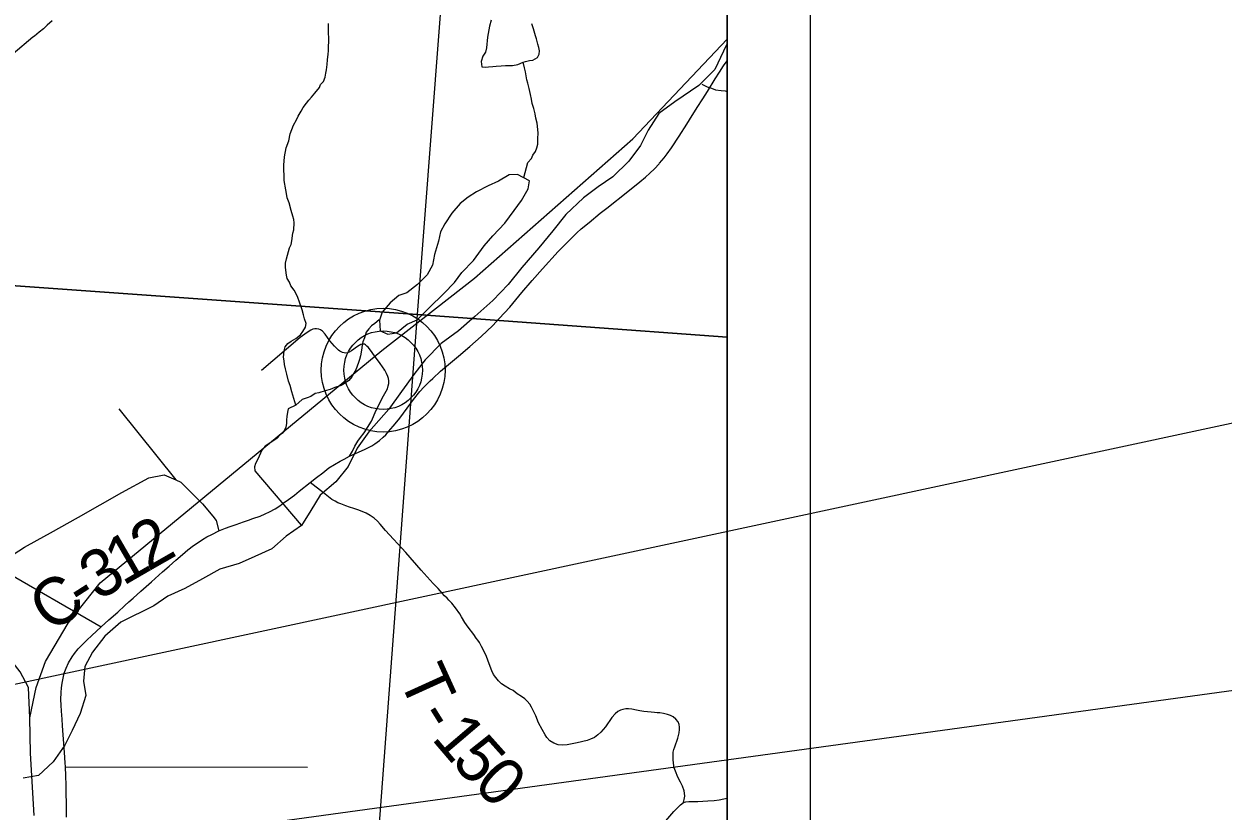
# Model space of a CAD drawing. Extents: x 0 to 44, y -23.8 to 22.
# Drawn here: x 8.055 to 9.496, y 17.755 to 18.701 of the extents above; entities that cross this region are included whole.
import ezdxf

# ---------------------------------------------------------------- set-up
doc = ezdxf.new("R2010")
doc.units = 0
for name, color, linetype in [('Default', 7, 'Continuous'), ('GM_X_County_Road', 7, 'Continuous'), ('GM_X_County_Road_Text', 7, 'Continuous'), ('GM_X_Minor_Lake', 7, 'Continuous'), ('GM_X_Minor_River', 7, 'Continuous'), ('GM_X_Rail_Line', 7, 'Continuous'), ('GM_X_Section', 7, 'Continuous'), ('GM_X_State_Route', 7, 'Continuous'), ('GM_X_Township_Road', 7, 'Continuous'), ('GM_X_Township_Road_Text', 7, 'Continuous'), ('GM_X_Unincorporated', 7, 'Continuous'), ('GM_X_Unincorporated_Location', 7, 'Continuous'), ('SH_Cut_Line', 7, 'Continuous'), ('SH_Data', 7, 'Continuous')]:
    doc.layers.add(name, color=color, linetype=linetype)

msp = doc.modelspace()

# ---------------------------------------------------------------- linework, layer by layer
at = {"layer": 'Default'}
msp.add_lwpolyline([(7.2787, 14.3616), (7.5613, 14.343), (8.045, 14.3111), (8.4778, 14.2825), (8.9, 14.2547), (8.9, 20.3521), (8.6785, 20.3684), (7.6577, 20.4476), (7.4495, 20.4611), (7.016, 20.4891)], dxfattribs=at)
for points in [[(8.9, 18.3242), (8.9, 19.3386), (8.6049, 19.3603), (8.5278, 18.3516)], [(8.9, 17.3085), (8.9, 18.3242), (8.5278, 18.3516), (8.4522, 17.3376)]]:
    msp.add_lwpolyline(points, close=True, dxfattribs=at)
at = {"layer": 'GM_X_County_Road'}
for points in [[(8.0828, 18.0867), (8.0837, 18.0872), (8.0873, 18.0892), (8.1208, 18.1078), (8.173, 18.1377), (8.2054, 18.1551), (8.224, 18.1588), (8.238, 18.1527), (8.2439, 18.1501), (8.27, 18.124), (8.2824, 18.1091), (8.2862, 18.1041), (8.2893, 18.0915)], [(8.0274, 18.0459), (8.0425, 18.0631), (8.0562, 18.0718), (8.0828, 18.0867)]]:
    msp.add_lwpolyline(points, dxfattribs=at)
at = {"layer": 'GM_X_Minor_Lake'}
for points in [[(8.6627, 18.512), (8.6483, 18.5196), (8.6384, 18.5192), (8.6255, 18.5116), (8.6129, 18.5059), (8.5989, 18.4987), (8.589, 18.4926), (8.5795, 18.485), (8.5696, 18.4733), (8.5608, 18.4603), (8.5559, 18.4508), (8.5532, 18.4394), (8.5486, 18.4235), (8.546, 18.4109), (8.5399, 18.3992), (8.5281, 18.3874), (8.5155, 18.3775), (8.5056, 18.3745), (8.4954, 18.3657), (8.4859, 18.3544), (8.4824, 18.3448), (8.4832, 18.3319), (8.4927, 18.3277), (8.503, 18.3296), (8.5159, 18.3399), (8.5277, 18.3452), (8.5421, 18.3596), (8.5596, 18.3767), (8.5725, 18.39), (8.5813, 18.4018), (8.5954, 18.4162), (8.6083, 18.4341), (8.6186, 18.4459), (8.633, 18.4614), (8.6444, 18.4766), (8.6532, 18.4884), (8.6612, 18.5025), (8.6627, 18.512)], [(8.4954, 18.3657), (8.4859, 18.3544), (8.4824, 18.3448), (8.4832, 18.3319), (8.4927, 18.3277), (8.503, 18.3296), (8.5159, 18.3399), (8.5277, 18.3452), (8.5421, 18.3596), (8.5596, 18.3767), (8.5725, 18.39), (8.5813, 18.4018), (8.5954, 18.4162), (8.6083, 18.4341), (8.6186, 18.4459), (8.633, 18.4614), (8.6444, 18.4766), (8.6532, 18.4884), (8.6612, 18.5025), (8.6627, 18.512)], [(8.6627, 18.512), (8.6483, 18.5196), (8.6384, 18.5192), (8.6255, 18.5116), (8.6129, 18.5059), (8.5989, 18.4987), (8.589, 18.4926), (8.5795, 18.485), (8.5696, 18.4733), (8.5608, 18.4603), (8.5559, 18.4508), (8.5532, 18.4394), (8.5486, 18.4235), (8.546, 18.4109), (8.5399, 18.3992), (8.5281, 18.3874), (8.5155, 18.3775), (8.5056, 18.3745), (8.4954, 18.3657)]]:
    msp.add_lwpolyline(points, dxfattribs=at)
at = {"layer": 'GM_X_Minor_River'}
for points in [[(8.382, 18.2426), (8.3772, 18.2586), (8.375, 18.2662), (8.3732, 18.2712), (8.371, 18.2796), (8.3696, 18.2861), (8.3685, 18.2914), (8.3678, 18.296), (8.3671, 18.3002), (8.3679, 18.3077), (8.3691, 18.3127), (8.3722, 18.3168), (8.3764, 18.3194), (8.3821, 18.3228), (8.3875, 18.3269), (8.3902, 18.331), (8.3937, 18.3363), (8.3945, 18.3405), (8.3926, 18.3462), (8.3912, 18.3511), (8.3894, 18.3569), (8.3883, 18.3607), (8.3868, 18.3653), (8.3839, 18.3733), (8.3798, 18.3809), (8.376, 18.3859), (8.3742, 18.3905), (8.3716, 18.3947), (8.3709, 18.3989), (8.3695, 18.408), (8.3695, 18.4133), (8.3707, 18.4183), (8.3743, 18.4315), (8.3762, 18.4357), (8.377, 18.4398), (8.3783, 18.4493), (8.3795, 18.4531), (8.3799, 18.4615), (8.3796, 18.4657), (8.3785, 18.4695), (8.3763, 18.4763), (8.3741, 18.4855), (8.3716, 18.4916), (8.3709, 18.4969), (8.3698, 18.5011), (8.368, 18.5125), (8.3675, 18.5315), (8.3679, 18.5357), (8.3683, 18.541), (8.3704, 18.5516), (8.3735, 18.5603), (8.3751, 18.5687), (8.379, 18.5789), (8.3829, 18.5853), (8.3848, 18.5898), (8.3883, 18.5959), (8.391, 18.6004), (8.3949, 18.6053), (8.3976, 18.609), (8.401, 18.6128), (8.4049, 18.6173), (8.4103, 18.6241), (8.4118, 18.6279), (8.4153, 18.6316), (8.4172, 18.6365), (8.4181, 18.6415), (8.4189, 18.6456), (8.4197, 18.6517), (8.4201, 18.6574), (8.421, 18.6642), (8.4214, 18.6684), (8.4216, 18.6847), (8.4213, 18.6889), (8.4214, 18.7011)], [(8.6168, 18.7051), (8.6148, 18.6979), (8.6129, 18.6892), (8.6124, 18.6846), (8.6111, 18.6721), (8.6099, 18.6668), (8.6068, 18.6619), (8.6045, 18.6554), (8.6056, 18.649), (8.6093, 18.6485), (8.6135, 18.6489), (8.6188, 18.6496), (8.6226, 18.6499), (8.6287, 18.6502), (8.6337, 18.6505), (8.6382, 18.6505), (8.6424, 18.6508), (8.6488, 18.6518), (8.6552, 18.6546)], [(8.6552, 18.6546), (8.658, 18.6555), (8.6626, 18.6566), (8.6667, 18.6569), (8.6725, 18.6603), (8.6744, 18.6641), (8.6748, 18.6682), (8.6741, 18.6724), (8.6726, 18.6762), (8.6712, 18.6827), (8.6701, 18.6865), (8.6675, 18.6949), (8.6657, 18.7006)], [(8.9, 18.6772), (8.8957, 18.6679), (8.8853, 18.6459), (8.8662, 18.6267), (8.8373, 18.6071), (8.8182, 18.5931), (8.8052, 18.5731), (8.796, 18.5545), (8.7822, 18.5356), (8.7627, 18.5167), (8.7452, 18.505), (8.7277, 18.4915), (8.7063, 18.4715), (8.6906, 18.4522), (8.6738, 18.4314), (8.6535, 18.4079), (8.6371, 18.3875), (8.6188, 18.3682), (8.597, 18.349), (8.5776, 18.332), (8.5566, 18.3166), (8.5375, 18.2969), (8.5237, 18.2795), (8.5088, 18.2591), (8.4939, 18.2379), (8.4698, 18.2103), (8.4556, 18.191), (8.4449, 18.1687), (8.43, 18.1505), (8.4113, 18.1343), (8.4002, 18.1161), (8.3887, 18.098), (8.3704, 18.0851), (8.3532, 18.07), (8.3327, 18.0607), (8.314, 18.0524), (8.2905, 18.0453), (8.2699, 18.034), (8.2486, 18.0224), (8.2284, 18.013), (8.2113, 18.0013), (8.1717, 17.9817), (8.1526, 17.9651), (8.1377, 17.9458), (8.1285, 17.9284), (8.1269, 17.911), (8.1298, 17.8935), (8.1228, 17.8719), (8.1132, 17.8518), (8.1044, 17.834), (8.0906, 17.814), (8.073, 17.7977), (8.0544, 17.7944)], [(8.656, 18.516), (8.6608, 18.5343), (8.665, 18.5388), (8.6666, 18.543), (8.67, 18.5475), (8.6716, 18.5516), (8.6728, 18.5562), (8.6729, 18.5626), (8.6733, 18.5698), (8.6719, 18.5813), (8.6705, 18.5874), (8.6694, 18.5927), (8.668, 18.5992), (8.6661, 18.6049), (8.6651, 18.6102), (8.664, 18.6159), (8.6622, 18.6232), (8.6607, 18.6293), (8.6596, 18.6335), (8.6586, 18.6384), (8.6578, 18.643), (8.6568, 18.6479), (8.6552, 18.6546)], [(8.8697, 18.6281), (8.8762, 18.625), (8.8815, 18.6234), (8.886, 18.6215), (8.8928, 18.6206), (8.8977, 18.6202), (8.9, 18.6196)], [(8.4822, 18.3451), (8.4768, 18.3406), (8.473, 18.338), (8.4695, 18.3342), (8.4664, 18.3304), (8.4645, 18.3236), (8.4625, 18.3187), (8.4617, 18.3145), (8.4609, 18.3088), (8.4597, 18.302), (8.4585, 18.2975), (8.4573, 18.2937), (8.4557, 18.2895), (8.4542, 18.285), (8.4515, 18.2809), (8.4491, 18.2767), (8.4457, 18.2722), (8.4403, 18.2685), (8.4365, 18.2662), (8.4289, 18.2637), (8.4232, 18.2615), (8.4174, 18.2596), (8.4095, 18.2574), (8.4053, 18.2564), (8.3999, 18.253), (8.3957, 18.2515), (8.3896, 18.2493), (8.382, 18.2426), (8.3728, 18.2382), (8.372, 18.234), (8.3712, 18.2291), (8.3708, 18.2249), (8.3707, 18.2207), (8.3699, 18.2162), (8.3668, 18.2094), (8.363, 18.2067), (8.3595, 18.203), (8.3545, 18.1992), (8.3499, 18.1966), (8.345, 18.1933), (8.3411, 18.1884), (8.3364, 18.1778), (8.3334, 18.1725), (8.3322, 18.1684), (8.3329, 18.1638), (8.3882, 18.0985)]]:
    msp.add_lwpolyline(points, dxfattribs=at)
at = {"layer": 'GM_X_Rail_Line'}
for points in [[(8.0624, 17.8667), (8.0701, 17.9031), (8.0811, 17.9347), (8.1085, 17.9806), (8.147, 18.0292), (8.4854, 18.3083), (8.5968, 18.3951), (8.787, 18.5626), (8.9, 18.6825)], [(8.0624, 17.8667), (8.061, 17.9033), (8.051, 17.922), (8.0356, 17.9418), (8.0181, 17.9517), (7.6833, 18.0613), (7.4877, 18.1275), (7.4357, 18.1458), (7.4001, 18.1557), (7.3576, 18.1574), (7.3191, 18.1482)], [(8.0676, 17.7494), (8.0634, 17.8242), (8.0624, 17.8667)]]:
    msp.add_lwpolyline(points, dxfattribs=at)
at = {"layer": 'GM_X_Section'}
for points in [[(7.5875, 19.4351), (8.6049, 19.3603), (8.5278, 18.3516), (7.5123, 18.4238)], [(7.5123, 18.4238), (8.5278, 18.3516), (8.4522, 17.3376), (7.4446, 17.3999)]]:
    msp.add_lwpolyline(points, close=True, dxfattribs=at)
at = {"layer": 'GM_X_State_Route'}
for points in [[(8.0892, 18.7044), (8.0834, 18.6991), (8.0788, 18.6948), (8.0736, 18.6909), (8.0679, 18.686), (8.066, 18.6846), (8.0422, 18.6645)], [(8.1481, 17.9761), (8.1575, 17.9845), (8.1681, 17.994), (8.1766, 18.002), (8.1814, 18.0061), (8.1864, 18.0106), (8.1957, 18.0189), (8.2087, 18.0304), (8.222, 18.0423), (8.2297, 18.049), (8.2379, 18.0564), (8.2457, 18.0631), (8.2524, 18.0688), (8.2591, 18.074), (8.2646, 18.0776), (8.2697, 18.0811), (8.2752, 18.0843), (8.281, 18.0873), (8.2893, 18.0915), (8.2976, 18.0948), (8.3032, 18.0968), (8.3103, 18.0993), (8.319, 18.1022), (8.3252, 18.1045), (8.3304, 18.1062), (8.3393, 18.1093), (8.345, 18.1118), (8.3502, 18.1142), (8.357, 18.118), (8.3628, 18.1214), (8.3667, 18.1246), (8.3732, 18.1292), (8.3803, 18.1343), (8.3859, 18.1392), (8.3992, 18.1496), (8.4068, 18.1555), (8.4143, 18.1614), (8.4218, 18.1674), (8.4285, 18.1713), (8.4352, 18.1753), (8.4399, 18.1778), (8.4464, 18.1811), (8.4653, 18.1898), (8.4685, 18.1913), (8.4732, 18.1936), (8.477, 18.1961), (8.4824, 18.2001), (8.4868, 18.2039), (8.4901, 18.207), (8.4939, 18.2111), (8.5014, 18.22), (8.507, 18.227), (8.5158, 18.2389), (8.5234, 18.2492), (8.5311, 18.259), (8.5358, 18.2642), (8.5434, 18.2718), (8.5464, 18.2747), (8.5559, 18.2833), (8.5679, 18.2934), (8.5775, 18.3016), (8.5912, 18.3129), (8.6047, 18.325), (8.6188, 18.3383), (8.6261, 18.3465), (8.6389, 18.3604), (8.6534, 18.3778), (8.6659, 18.3924), (8.6782, 18.4062), (8.6972, 18.427), (8.709, 18.4393), (8.7151, 18.4453), (8.7196, 18.4496), (8.7248, 18.4544), (8.7343, 18.4622), (8.7477, 18.4731), (8.7557, 18.4794), (8.7807, 18.4991), (8.7953, 18.5108), (8.8019, 18.5164), (8.8074, 18.5213), (8.8127, 18.5266), (8.8185, 18.5327), (8.8191, 18.5333), (8.8244, 18.5398), (8.8282, 18.5446), (8.8334, 18.5519), (8.8424, 18.5656), (8.8516, 18.5801), (8.8549, 18.5853), (8.8643, 18.6004), (8.8708, 18.6108), (8.8764, 18.6196), (8.8859, 18.6346), (8.8909, 18.6426), (8.8957, 18.6501), (8.9, 18.6563)], [(7.9198, 18.1171), (7.926, 18.1143), (7.9489, 18.1004), (8.0274, 18.0459), (8.1481, 17.9761)], [(8.1063, 17.7476), (8.1063, 17.7628), (8.1062, 17.7775), (8.1061, 17.7859), (8.1058, 17.797), (8.1051, 17.808), (8.1049, 17.8126), (8.104, 17.8252), (8.1032, 17.836), (8.1025, 17.8465), (8.1017, 17.8574), (8.1012, 17.8652), (8.1005, 17.8747), (8.1, 17.8821), (8.0998, 17.8889), (8.0999, 17.8971), (8.1003, 17.9027), (8.1011, 17.9084), (8.1023, 17.9146), (8.1038, 17.9204), (8.1061, 17.9265), (8.1089, 17.9328), (8.1133, 17.9401), (8.1161, 17.9443), (8.1206, 17.9497), (8.1255, 17.955), (8.1309, 17.9601), (8.1371, 17.9659), (8.1481, 17.9761)]]:
    msp.add_lwpolyline(points, dxfattribs=at)
at = {"layer": 'GM_X_Township_Road'}
for p, q in [((8.1693, 18.2383), (8.238, 18.1527)), ((8.1051, 17.808), (8.3959, 17.8075))]:
    msp.add_line(p, q, dxfattribs=at)
for points in [[(8.4643, 18.3157), (8.4624, 18.316), (8.4599, 18.3156), (8.4559, 18.3131), (8.449, 18.3079), (8.446, 18.3062), (8.4441, 18.3053), (8.4417, 18.305), (8.4402, 18.3053), (8.438, 18.306), (8.4364, 18.3065), (8.4349, 18.3075), (8.4332, 18.3087), (8.4307, 18.3109), (8.4285, 18.3133), (8.423, 18.32), (8.4174, 18.3277), (8.4141, 18.3315), (8.4115, 18.333), (8.4095, 18.3337), (8.4067, 18.3344), (8.4047, 18.3343), (8.4023, 18.3337), (8.4001, 18.3326), (8.3958, 18.3298), (8.3873, 18.324), (8.3844, 18.3216), (8.3409, 18.2843)], [(8.4464, 18.1811), (8.45, 18.1872), (8.4529, 18.1932), (8.4563, 18.1991), (8.4597, 18.2038), (8.4642, 18.2094), (8.4728, 18.2234), (8.4786, 18.2367), (8.4874, 18.2537), (8.4923, 18.2623), (8.4931, 18.2658), (8.4936, 18.2685), (8.4938, 18.2719), (8.4935, 18.2745), (8.4926, 18.2771), (8.4911, 18.2807), (8.4889, 18.2847), (8.4834, 18.2927), (8.4767, 18.3018), (8.4715, 18.3087), (8.4687, 18.3121), (8.4673, 18.3136), (8.4656, 18.3151), (8.4643, 18.3157)], [(8.8479, 17.7651), (8.8489, 17.7709), (8.8493, 17.7727), (8.8491, 17.7764), (8.8484, 17.7792), (8.8466, 17.7846), (8.8442, 17.7895), (8.841, 17.7954), (8.8381, 17.8027), (8.8367, 17.8068), (8.8356, 17.8124), (8.8352, 17.8166), (8.8352, 17.8207), (8.8355, 17.8254), (8.8361, 17.8289), (8.8373, 17.8322), (8.8386, 17.8356), (8.8398, 17.839), (8.841, 17.8426), (8.8419, 17.8457), (8.8426, 17.8489), (8.8431, 17.8528), (8.8431, 17.8556), (8.8425, 17.859), (8.8413, 17.8621), (8.8387, 17.8651), (8.8355, 17.8681), (8.832, 17.8695), (8.8285, 17.871), (8.8236, 17.8719), (8.8194, 17.8727), (8.8159, 17.873), (8.8128, 17.8732), (8.8088, 17.8736), (8.8045, 17.8739), (8.7999, 17.8746), (8.7953, 17.8754), (8.7911, 17.8762), (8.7856, 17.8773), (8.7818, 17.8778), (8.7786, 17.8778), (8.7748, 17.8769), (8.7719, 17.8761), (8.769, 17.8744), (8.7657, 17.8718), (8.7615, 17.8672), (8.7539, 17.8561), (8.7486, 17.8498), (8.745, 17.8463), (8.741, 17.8434), (8.7359, 17.8411), (8.7319, 17.8398), (8.7201, 17.8369), (8.708, 17.8345), (8.7021, 17.8339), (8.6971, 17.8346), (8.692, 17.8366), (8.6873, 17.8392), (8.6836, 17.8431), (8.6814, 17.8465), (8.6778, 17.8528), (8.6737, 17.8609), (8.6702, 17.8694), (8.6671, 17.8756), (8.6652, 17.8796), (8.663, 17.8833), (8.6601, 17.8868), (8.6571, 17.8896), (8.6531, 17.8926), (8.6481, 17.8958), (8.6429, 17.8995), (8.6385, 17.9018), (8.6333, 17.9049), (8.629, 17.9079), (8.6255, 17.9113), (8.6221, 17.9152), (8.6196, 17.9188), (8.6175, 17.9234), (8.613, 17.935), (8.6105, 17.9419), (8.6051, 17.9524), (8.6025, 17.9575), (8.6006, 17.9603), (8.5986, 17.9625), (8.5957, 17.9671), (8.5892, 17.9757), (8.585, 17.9815), (8.581, 17.9884), (8.5789, 17.9918), (8.5738, 17.9989), (8.5693, 18.0045), (8.566, 18.0082), (8.5638, 18.0105), (8.5606, 18.0133), (8.5576, 18.0168), (8.5529, 18.0224), (8.5469, 18.0284), (8.5327, 18.0444), (8.514, 18.0654), (8.4899, 18.092), (8.4835, 18.0994), (8.48, 18.1032), (8.4759, 18.1068), (8.4712, 18.1101), (8.4664, 18.1127), (8.4616, 18.1149), (8.4566, 18.1167), (8.4516, 18.1182), (8.4463, 18.12), (8.4419, 18.1215), (8.4362, 18.1238), (8.4324, 18.1253), (8.4291, 18.1272), (8.4254, 18.1292), (8.4213, 18.1322), (8.4151, 18.1374), (8.3992, 18.1496)], [(8.8213, 17.7365), (8.8265, 17.7432), (8.8363, 17.7545), (8.8392, 17.7577), (8.844, 17.7623), (8.8479, 17.7651)], [(8.8479, 17.7651), (8.8504, 17.7658), (8.854, 17.7662), (8.8553, 17.7663), (8.8603, 17.7663), (8.8651, 17.7663), (8.877, 17.7671), (8.8846, 17.7677), (8.8904, 17.7684), (8.8963, 17.7695), (8.9, 17.7704)]]:
    msp.add_lwpolyline(points, dxfattribs=at)
at = {"layer": 'GM_X_Unincorporated'}
for radius in [0.0744, 0.0472]:
    msp.add_circle((8.4869, 18.2846), radius, dxfattribs=at)
at = {"layer": 'GM_X_Unincorporated_Location'}
msp.add_line((8.4869, 18.2846), (8.4869, 18.2846), dxfattribs=at)
at = {"layer": 'SH_Cut_Line'}
msp.add_lwpolyline([(2.838, 14.1), (8.9, 14.1), (8.9, 20.9), (6.8158, 20.9)], dxfattribs=at)
at = {"layer": 'SH_Data'}
for p, q in [((9, 21), (9, 14)), ((8.9, 20.9), (8.9, 14.1))]:
    msp.add_line(p, q, dxfattribs=at)
msp.add_lwpolyline([(5.3413, 17.3275), (9.7799, 18.2797), (9.7799, 17.9369)], close=True, dxfattribs=at)

# ---------------------------------------------------------------- texts
at = {"layer": 'GM_X_County_Road_Text'}
for s, rotation, p in [('2', 29.7271, (8.2045, 18.0423)), ('1', 30.1118, (8.1743, 18.0248)), ('3', 31.4841, (8.1448, 18.0067)), ('C', 35.3335, (8.088, 17.9676)), ('-', 32.7981, (8.1255, 17.9942))]:
    msp.add_text(s, height=0.0568, rotation=rotation, dxfattribs=at).set_placement(p)
at = {"layer": 'GM_X_Township_Road_Text'}
for s, rotation, p in [('T', 294.4333, (8.5048, 17.9148)), ('-', 301.9874, (8.5262, 17.8689)), ('1', 310.4588, (8.544, 17.8418)), ('5', 311.8019, (8.5677, 17.814)), ('0', 315.4946, (8.5938, 17.785))]:
    msp.add_text(s, height=0.0568, rotation=rotation, dxfattribs=at).set_placement(p)

doc.saveas('drawing.dxf')
